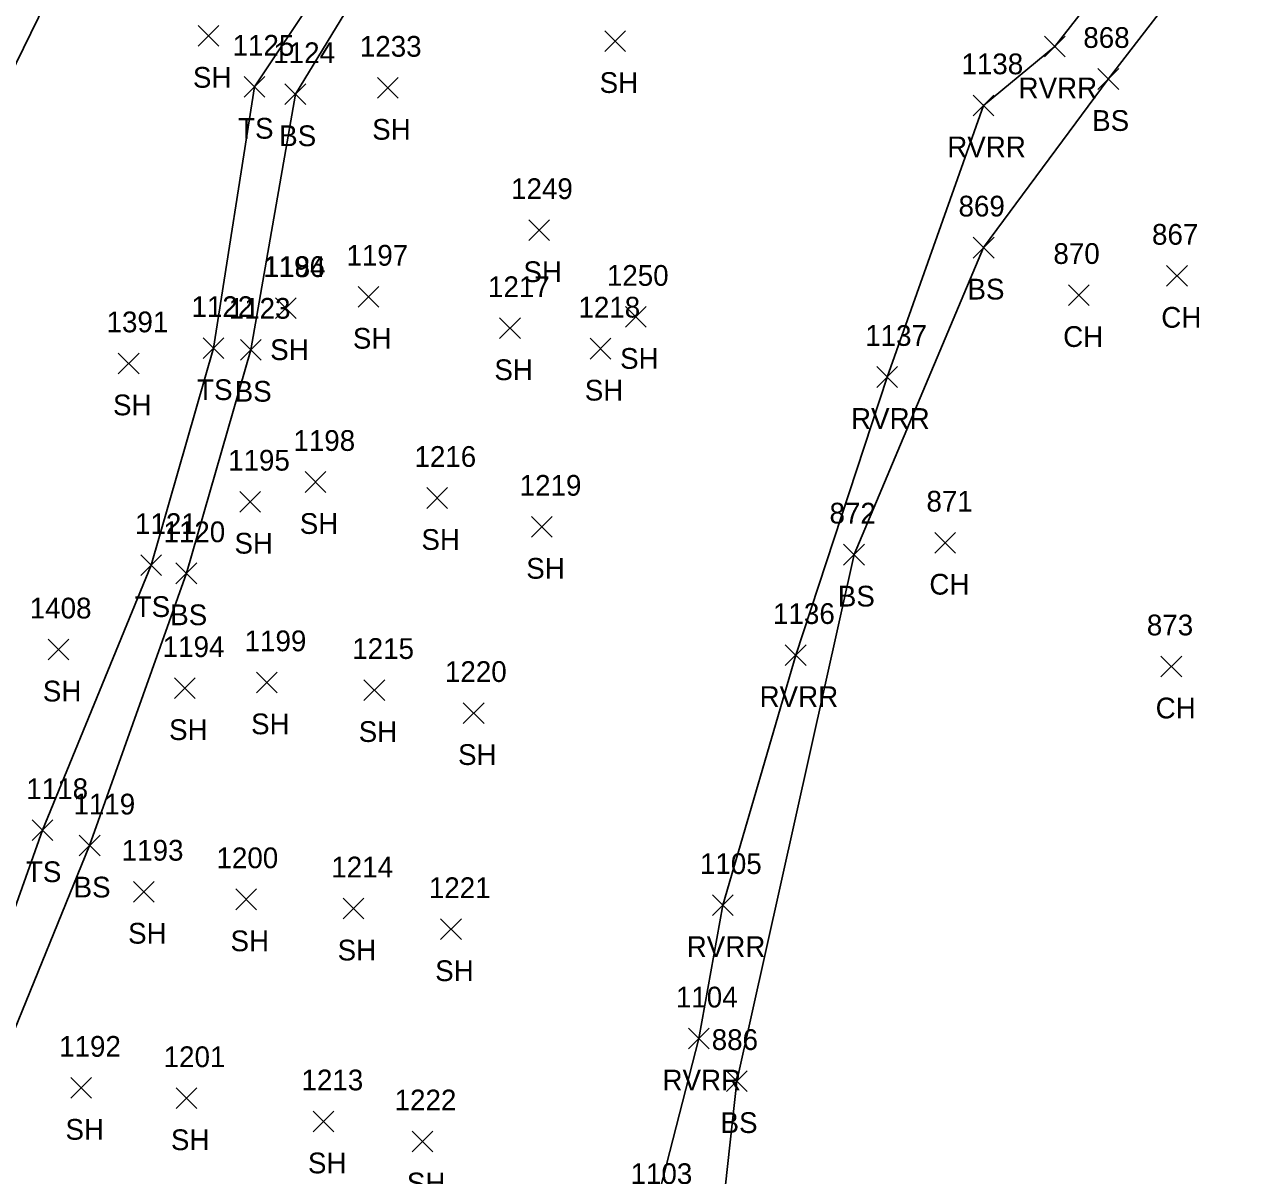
# Model space of a CAD drawing. Extents: x 1885914 to 1887218, y 756253 to 760620.
# Drawn here: x 1886583 to 1886700.7, y 759954.5 to 760065.4 of the extents above; entities that cross this region are included whole.
import ezdxf

# ---------------------------------------------------------------- set-up
doc = ezdxf.new("R2010")
doc.units = 0
for name, color, linetype in [('L_A', 7, 'Continuous'), ('L_I', 7, 'Continuous'), ('L_TIC', 7, 'Continuous'), ('LAWE', 7, 'Continuous'), ('LELB', 7, 'Continuous')]:
    doc.layers.add(name, color=color, linetype=linetype)

msp = doc.modelspace()

# ---------------------------------------------------------------- linework, layer by layer
at = {"layer": 'L_TIC'}
for points in [[(1886599.71, 760063.32), (1886601.71, 760065.32)], [(1886601.71, 760063.32), (1886599.71, 760065.32)], [(1886638.89, 760062.82), (1886640.89, 760064.82)], [(1886640.89, 760062.82), (1886638.89, 760064.82)], [(1886681.23, 760062.3), (1886683.23, 760064.3)], [(1886683.23, 760062.3), (1886681.23, 760064.3)], [(1886686.39, 760059.16), (1886688.39, 760061.16)], [(1886688.39, 760059.16), (1886686.39, 760061.16)], [(1886604.14, 760058.41), (1886606.14, 760060.41)], [(1886606.14, 760058.41), (1886604.14, 760060.41)], [(1886616.98, 760058.31), (1886618.98, 760060.31)], [(1886618.98, 760058.31), (1886616.98, 760060.31)], [(1886608.07, 760057.69), (1886610.07, 760059.69)], [(1886610.07, 760057.69), (1886608.07, 760059.69)], [(1886674.36, 760056.62), (1886676.36, 760058.62)], [(1886676.36, 760056.62), (1886674.36, 760058.62)], [(1886631.55, 760044.59), (1886633.55, 760046.59)], [(1886633.55, 760044.59), (1886631.55, 760046.59)], [(1886674.38, 760042.91), (1886676.38, 760044.91)], [(1886676.38, 760042.91), (1886674.38, 760044.91)], [(1886693.01, 760040.19), (1886695.01, 760042.19)], [(1886695.01, 760040.19), (1886693.01, 760042.19)], [(1886615.12, 760038.17), (1886617.12, 760040.17)], [(1886617.12, 760038.17), (1886615.12, 760040.17)], [(1886683.55, 760038.34), (1886685.55, 760040.34)], [(1886685.55, 760038.34), (1886683.55, 760040.34)], [(1886607.15, 760037.08), (1886609.15, 760039.08)], [(1886609.15, 760037.08), (1886607.15, 760039.08)], [(1886607.16, 760037.07), (1886609.16, 760039.07)], [(1886609.16, 760037.07), (1886607.16, 760039.07)], [(1886640.86, 760036.23), (1886642.86, 760038.23)], [(1886642.86, 760036.23), (1886640.86, 760038.23)], [(1886628.75, 760035.14), (1886630.75, 760037.14)], [(1886630.75, 760035.14), (1886628.75, 760037.14)], [(1886600.19, 760033.22), (1886602.19, 760035.22)], [(1886602.19, 760033.22), (1886600.19, 760035.22)], [(1886603.77, 760033.06), (1886605.77, 760035.06)], [(1886605.77, 760033.06), (1886603.77, 760035.06)], [(1886637.46, 760033.17), (1886639.46, 760035.17)], [(1886639.46, 760033.17), (1886637.46, 760035.17)], [(1886592.01, 760031.75), (1886594.01, 760033.75)], [(1886594.01, 760031.75), (1886592.01, 760033.75)], [(1886665.09, 760030.44), (1886667.09, 760032.44)], [(1886667.09, 760030.44), (1886665.09, 760032.44)], [(1886610.01, 760020.32), (1886612.01, 760022.32)], [(1886612.01, 760020.32), (1886610.01, 760022.32)], [(1886603.71, 760018.42), (1886605.71, 760020.42)], [(1886605.71, 760018.42), (1886603.71, 760020.42)], [(1886621.72, 760018.78), (1886623.72, 760020.78)], [(1886623.72, 760018.78), (1886621.72, 760020.78)], [(1886631.82, 760016), (1886633.82, 760018)], [(1886633.82, 760016), (1886631.82, 760018)], [(1886670.67, 760014.47), (1886672.67, 760016.47)], [(1886672.67, 760014.47), (1886670.67, 760016.47)], [(1886661.89, 760013.32), (1886663.89, 760015.32)], [(1886663.89, 760013.32), (1886661.89, 760015.32)], [(1886594.18, 760012.31), (1886596.18, 760014.31)], [(1886596.18, 760012.31), (1886594.18, 760014.31)], [(1886597.57, 760011.52), (1886599.57, 760013.52)], [(1886599.57, 760011.52), (1886597.57, 760013.52)], [(1886585.25, 760004.17), (1886587.25, 760006.17)], [(1886587.25, 760004.17), (1886585.25, 760006.17)], [(1886656.27, 760003.64), (1886658.27, 760005.64)], [(1886658.27, 760003.64), (1886656.27, 760005.64)], [(1886692.46, 760002.54), (1886694.46, 760004.54)], [(1886694.46, 760002.54), (1886692.46, 760004.54)], [(1886597.41, 760000.45), (1886599.41, 760002.45)], [(1886599.41, 760000.45), (1886597.41, 760002.45)], [(1886605.31, 760001.01), (1886607.31, 760003.01)], [(1886607.31, 760001.01), (1886605.31, 760003.01)], [(1886615.68, 760000.27), (1886617.68, 760002.27)], [(1886617.68, 760000.27), (1886615.68, 760002.27)], [(1886625.25, 759998.05), (1886627.25, 760000.05)], [(1886627.25, 759998.05), (1886625.25, 760000.05)], [(1886583.71, 759986.76), (1886585.71, 759988.76)], [(1886585.71, 759986.76), (1886583.71, 759988.76)], [(1886588.25, 759985.28), (1886590.25, 759987.28)], [(1886590.25, 759985.28), (1886588.25, 759987.28)], [(1886593.46, 759980.83), (1886595.46, 759982.83)], [(1886595.46, 759980.83), (1886593.46, 759982.83)], [(1886603.33, 759980.1), (1886605.33, 759982.1)], [(1886605.33, 759980.1), (1886603.33, 759982.1)], [(1886613.66, 759979.21), (1886615.66, 759981.21)], [(1886615.66, 759979.21), (1886613.66, 759981.21)], [(1886649.25, 759979.54), (1886651.25, 759981.54)], [(1886651.25, 759979.54), (1886649.25, 759981.54)], [(1886623.06, 759977.22), (1886625.06, 759979.22)], [(1886625.06, 759977.22), (1886623.06, 759979.22)], [(1886646.93, 759966.68), (1886648.93, 759968.68)], [(1886648.93, 759966.68), (1886646.93, 759968.68)], [(1886650.59, 759962.58), (1886652.59, 759964.58)], [(1886652.59, 759962.58), (1886650.59, 759964.58)], [(1886587.43, 759961.93), (1886589.43, 759963.93)], [(1886589.43, 759961.93), (1886587.43, 759963.93)], [(1886597.59, 759960.93), (1886599.59, 759962.93)], [(1886599.59, 759960.93), (1886597.59, 759962.93)], [(1886610.79, 759958.69), (1886612.79, 759960.69)], [(1886612.79, 759958.69), (1886610.79, 759960.69)], [(1886620.32, 759956.76), (1886622.32, 759958.76)], [(1886622.32, 759956.76), (1886620.32, 759958.76)]]:
    msp.add_lwpolyline(points, dxfattribs=at)
at = {"layer": 'LAWE'}
msp.add_lwpolyline([(1886643.57, 759950.66), (1886647.93, 759967.68), (1886650.25, 759980.54), (1886657.27, 760004.64), (1886666.09, 760031.44), (1886675.36, 760057.62), (1886682.23, 760063.3), (1886696.4, 760081.41), (1886713.46, 760096.25), (1886729.03, 760111.8), (1886751.04, 760124.89), (1886757.81, 760125.78), (1886762.25, 760134.23), (1886778.71, 760146.09), (1886791.91, 760151.37), (1886806.2, 760167.73), (1886818.04, 760166.72), (1886829.4, 760164.97), (1886849.11, 760176.99)], dxfattribs=at)
at = {"layer": 'LELB'}
for points in [[(1886725.27, 760338.09), (1886712.33, 760310.28), (1886698.46, 760286.41), (1886683.25, 760252.31), (1886665.56, 760220.6), (1886649.26, 760186.3), (1886631.93, 760155.48), (1886614.95, 760123.77), (1886599.48, 760094.94), (1886586.46, 760070.53), (1886572.04, 760041.07), (1886559.72, 760022.59), (1886545.87, 759996.97), (1886529.41, 759963.14), (1886510.6, 759921.25), (1886501.24, 759900.36), (1886492.69, 759872.91), (1886485.39, 759846.95), (1886480.56, 759824.59), (1886476.3, 759808.27), (1886477.13, 759795.21)], [(1887191.67, 760127.4), (1887162.59, 760142.97), (1887139.96, 760151.52), (1887098.78, 760169.34), (1887064.77, 760179.63), (1887039.44, 760184.45), (1887015.43, 760186.04), (1886988.17, 760195.78), (1886958.13, 760192.47), (1886941.93, 760196.3), (1886915.34, 760186.03), (1886875.72, 760169.95), (1886843.17, 760163.26), (1886814.02, 760157.37), (1886794.47, 760144.1), (1886725.54, 760103.53), (1886704.64, 760082.53), (1886687.39, 760060.16), (1886675.38, 760043.91), (1886662.89, 760014.32), (1886651.59, 759963.58), (1886647.85, 759929.2)], [(1886569.47, 759932.79), (1886578.55, 759960.06), (1886589.25, 759986.28), (1886598.57, 760012.52), (1886604.77, 760034.06), (1886609.07, 760058.69), (1886625.15, 760085.1), (1886640.42, 760091.38), (1886649.45, 760109.89), (1886661.77, 760128.12), (1886683.78, 760144.02), (1886702.73, 760156.3), (1886717, 760162.7), (1886740.68, 760172.2), (1886760.93, 760185.46), (1886776.22, 760178.86), (1886795.79, 760185.28), (1886813.44, 760184.92), (1886834.73, 760176.46), (1886849.11, 760176.99)], [(1886572.3, 759803.95), (1886568.6, 759823.21), (1886564.73, 759854.7), (1886563.87, 759883.9), (1886566.65, 759905.78), (1886566.1, 759932.48), (1886575.22, 759961.15), (1886584.71, 759987.76), (1886595.18, 760013.31), (1886601.19, 760034.22), (1886605.14, 760059.41), (1886622.97, 760086.15), (1886635.93, 760094.98), (1886646.75, 760112.81), (1886658.85, 760130.9), (1886680.3, 760148.52), (1886699.66, 760159.95), (1886715.31, 760165.82), (1886739.18, 760176.38)]]:
    msp.add_lwpolyline(points, dxfattribs=at)

# ---------------------------------------------------------------- texts
at = {"layer": 'L_A'}
for s, p in [('SH', (1886599.2, 760059.32)), ('SH', (1886638.38, 760058.82)), ('RVRR', (1886678.74, 760058.3)), ('TS', (1886603.55, 760054.41)), ('SH', (1886616.47, 760054.31)), ('BS', (1886685.83, 760055.16)), ('BS', (1886607.51, 760053.69)), ('RVRR', (1886671.87, 760052.62)), ('SH', (1886631.04, 760040.59)), ('BS', (1886673.82, 760038.91)), ('CH', (1886692.49, 760036.19)), ('SH', (1886614.61, 760034.17)), ('CH', (1886683.04, 760034.34)), ('SH', (1886606.64, 760033.08)), ('SH', (1886606.65, 760033.07)), ('SH', (1886640.35, 760032.23)), ('SH', (1886628.24, 760031.14)), ('TS', (1886599.6, 760029.22)), ('BS', (1886603.22, 760029.06)), ('SH', (1886636.95, 760029.17)), ('SH', (1886591.5, 760027.75)), ('RVRR', (1886662.6, 760026.44)), ('SH', (1886609.49, 760016.32)), ('SH', (1886603.2, 760014.42)), ('SH', (1886621.21, 760014.78)), ('SH', (1886631.31, 760012)), ('CH', (1886670.15, 760010.47)), ('TS', (1886593.59, 760008.31)), ('BS', (1886661.33, 760009.32)), ('BS', (1886597.01, 760007.52)), ('SH', (1886584.74, 760000.17)), ('RVRR', (1886653.79, 759999.64)), ('CH', (1886691.95, 759998.54)), ('SH', (1886604.8, 759997.01)), ('SH', (1886596.9, 759996.45)), ('SH', (1886615.17, 759996.27)), ('SH', (1886624.74, 759994.05)), ('TS', (1886583.11, 759982.76)), ('BS', (1886587.7, 759981.28)), ('SH', (1886592.95, 759976.83)), ('SH', (1886602.82, 759976.1)), ('RVRR', (1886646.77, 759975.54)), ('SH', (1886613.14, 759975.21)), ('SH', (1886622.54, 759973.22)), ('RVRR', (1886644.44, 759962.68)), ('SH', (1886586.92, 759957.93)), ('BS', (1886650.03, 759958.58)), ('SH', (1886597.08, 759956.93)), ('SH', (1886610.28, 759954.69)), ('SH', (1886619.81, 759952.76))]:
    msp.add_text(s, height=2, dxfattribs=at).set_placement(p)
at = {"layer": 'L_I'}
for s, p in [('1125', (1886603.02, 760062.41)), ('868', (1886684.98, 760063.16)), ('1124', (1886606.94, 760061.69)), ('1233', (1886615.28, 760062.31)), ('1138', (1886673.24, 760060.62)), ('1249', (1886629.85, 760048.59)), ('869', (1886672.96, 760046.91)), ('867', (1886691.6, 760044.19)), ('1197', (1886613.99, 760042.17)), ('870', (1886682.1, 760042.34)), ('1196', (1886605.97, 760041.08)), ('1184', (1886606.03, 760041.07)), ('1250', (1886639.08, 760040.23)), ('1217', (1886627.63, 760039.14)), ('1122', (1886599.06, 760037.22)), ('1123', (1886602.65, 760037.06)), ('1218', (1886636.34, 760037.17)), ('1391', (1886590.88, 760035.75)), ('1137', (1886663.97, 760034.44)), ('1198', (1886608.88, 760024.32)), ('1195', (1886602.59, 760022.42)), ('1216', (1886620.54, 760022.78)), ('1219', (1886630.68, 760020)), ('871', (1886669.87, 760018.47)), ('872', (1886660.53, 760017.32)), ('1121', (1886593.62, 760016.31)), ('1120', (1886596.36, 760015.52)), ('1408', (1886583.48, 760008.17)), ('1136', (1886655.09, 760007.64)), ('873', (1886691.1, 760006.54)), ('1199', (1886604.18, 760005.01)), ('1194', (1886596.29, 760004.45)), ('1215', (1886614.55, 760004.27)), ('1220', (1886623.48, 760002.05)), ('1118', (1886583.15, 759990.76)), ('1119', (1886587.69, 759989.28)), ('1193', (1886592.34, 759984.83)), ('1200', (1886601.47, 759984.1)), ('1105', (1886648.05, 759983.54)), ('1214', (1886612.53, 759983.21)), ('1221', (1886621.93, 759981.22)), ('1104', (1886645.73, 759970.68)), ('1192', (1886586.31, 759965.93)), ('886', (1886649.18, 759966.58)), ('1201', (1886596.38, 759964.93)), ('1213', (1886609.66, 759962.69)), ('1222', (1886618.63, 759960.76)), ('1103', (1886641.36, 759953.66))]:
    msp.add_text(s, height=2, dxfattribs=at).set_placement(p)

doc.saveas('drawing.dxf')
